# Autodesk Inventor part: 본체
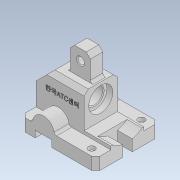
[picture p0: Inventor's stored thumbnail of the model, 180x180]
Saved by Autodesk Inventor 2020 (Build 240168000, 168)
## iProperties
Created: 2022-08
Part Number: 본체
Material: 일반
Document SubType Name: Modeling
Designer: user
Density: 1 g/cm^3
Appearance: 기본값
Author: user
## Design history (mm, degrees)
sketch "스케치1"
  geometry: L1 (32, -27)-(-58, -27); L2 (-58, -27)-(-58, -42); L3 (-58, -42)-(32, -42); L4 (32, -42)-(32, -27); L5 (32, -27)-(-58, -42); L6 (-58, -27)-(32, -42); C1 r 13 at (-31, -27); 4 further points
  constraints: 12 end point, 2 midpoint, 2 parallel, 1 centre point, 1 horizontal, 1 perpendicular, 1 point on line
  dimensions: "d0" = 15 distance of L1.end L2.end; "d1" = 90 distance of L2.end L3.end; "d2" = 26 diameter of C1; "d3" = 27 distance from line of C1.centre L2; "d4" = 42 distance from line of L3 point (0, 0); "d5" = 32 distance from line of L4 point (0, 0)
extrude "돌출1" new body sketch "스케치1" stored distance "d6" = 76; taper "d7" = 0 deg
sketch "스케치2"
  geometry: L1 (0, 18)-(-58, 18); L2 (-58, 18)-(-58, -27); L3 (-58, -27)-(0, -27); L4 (0, -27)-(0, 18); L5 (0, 18)-(-58, -27); L6 (-58, 18)-(0, -27); 3 further points
  constraints: 12 end point, 2 midpoint, 2 parallel, 1 coincident, 1 horizontal, 1 perpendicular, 1 vertical alignment
  dimensions: "d8" = 45 distance of L1.end L2.end
extrude "돌출2" join sketch "스케치2" stored distance "d9" = 40; taper "d10" = 0 deg
chamfer "모따기1" distance "d11" = 18; stored, may be unused: second distance "d12" = 2, angle "d13" = 45 deg
sketch "스케치3"
  geometry: C1 r 14.5 at (20, 27); 1 further point
  constraints: 1 centre point, 1 coincident
  dimensions: "d14" = 29 diameter of C1
extrude "돌출3" cut sketch "스케치3" distance "d15" = 7; taper "d16" = 0 deg
sketch "스케치4"
  geometry: C1 r 10 at (0, 0); 1 further point
  constraints: 1 centre point, 1 coincident
  dimensions: "d17" = 20 diameter of C1
extrude "돌출4" cut sketch "스케치4" extent not by distance; stored distance "d18" = 0; taper "d19" = 0 deg
sketch "스케치5"
  geometry: L1 (-5, 27.5)-(-29, 27.5); L2 (-29, 27.5)-(-29, 12.5); L3 (-29, 12.5)-(-5, 12.5); L4 (-5, 12.5)-(-5, 27.5); L5 (-5, 27.5)-(-29, 12.5); L6 (-29, 27.5)-(-5, 12.5); L7 (0, 40)-(0, 0) reference; 4 further points
  constraints: 12 end point, 4 midpoint, 2 parallel, 1 horizontal, 1 horizontal alignment, 1 perpendicular
  dimensions: "d20" = 5 distance between parallel lines of L7 L4; "d21" = 24 distance of L1.start L1.end; "d22" = 15 distance of L1.end L2.end
extrude "돌출5" join sketch "스케치5" distance "d23" = 30; taper "d24" = 0 deg
chamfer "모따기2" distance "d25" = 5; stored, may be unused: second distance "d26" = 2, angle "d27" = 45 deg
sketch "스케치6"
  geometry: L1 (24, 0)-(24, 25) reference; C1 r 4 at (12, 17); 1 further point
  constraints: 1 centre point
  dimensions: "d28" = 8 diameter of C1; "d29" = 35 vertical distance of C1.centre point (29, -18); "d30" = 12 distance from line of L1 C1.centre
extrude "돌출6" cut sketch "스케치6" extent not by distance; stored distance "d31" = 0; taper "d32" = 0 deg
chamfer "모따기3" distance "d33" = 1; stored, may be unused: second distance "d34" = 2, angle "d35" = 45 deg
sketch "스케치7"
  geometry: L1 (76, 15)-(0, 15) reference; L2 (58, 19)-(18, 19); L3 (18, 19)-(18, 15); L4 (18, 15)-(58, 15); L5 (58, 15)-(58, 19); L6 (58, 19)-(18, 15); L7 (18, 19)-(58, 15); L8 (18, 15)-(18, 60) reference; L9 (58, 60)-(58, 15) reference; L10 (58, 60)-(18, 60) reference; L11 (76, 0)-(0, 0) reference; 4 further points
  constraints: 12 end point, 2 midpoint, 2 parallel, 2 point on line, 1 horizontal, 1 perpendicular
  dimensions: "d36" = 45 distance between parallel lines of L4 L10; "d37" = 19 distance between parallel lines of L2 L11
extrude "돌출7" join sketch "스케치7" distance "d38" = 32; taper "d39" = 0 deg
sketch "스케치8"
  geometry: C1 r 29 at (38, 42); 1 further point
  constraints: 1 centre point, 1 coincident
  dimensions: "d40" = 58 diameter of C1
extrude "돌출8" cut sketch "스케치8" distance "d41" = 18; taper "d42" = 0 deg
sketch "스케치9"
  geometry: L1 (44, 19)-(32, 19); L2 (32, 19)-(32, 0); L3 (32, 0)-(44, 0); L4 (44, 0)-(44, 19); L5 (44, 19)-(32, 0); L6 (32, 19)-(44, 0); L7 (76, 0)-(0, 0) reference; L8 (20.336, 19)-(55.664, 19) reference; 3 further points
  constraints: 12 end point, 3 midpoint, 2 parallel, 2 point on line, 1 horizontal, 1 perpendicular, 1 vertical alignment
  dimensions: "d43" = 12 distance of L2.end L3.end
extrude "돌출9" cut sketch "스케치9" distance "d44" = 18; taper "d45" = 0 deg
sketch "스케치10"
  geometry: L1 (50, 76)-(50, 58) reference; 3 further points
  constraints: 1 vertical alignment
  dimensions: "d46" = 13 distance from line of L1 point (37, 68); "d47" = 30 vertical distance of point (37, 68) point (18, 38); "d48" = 60 distance of point (37, 8) point (37, 68)
hole "구멍1" sketch "스케치10" at (37, 68), (37, 8) diameter "d49" = 4.5; stored, may be unused: countersink angle "d53" = 90 deg, drill point angle "d55" = 118 deg; dims "d50" = 6, "d51" = 8, "d52" = 4.4, "d54" = 8
chamfer "모따기4" distance "d56" = 5; stored, may be unused: second distance "d57" = 2, angle "d58" = 45 deg
sketch "스케치11"
  geometry: L1 (-21, -34)-(-41, -34); L2 (-41, -34)-(-41, -42); L3 (-41, -42)-(-21, -42); L4 (-21, -42)-(-21, -34); L5 (-21, -34)-(-41, -42); L6 (-41, -34)-(-21, -42); L7 (-58, -27)-(-58, -42) reference; L8 (-53, -42)-(27, -42) reference; 2 further points
  constraints: 12 end point, 2 midpoint, 2 parallel, 1 horizontal, 1 perpendicular, 1 point on line
  dimensions: "d59" = 27 distance from line of point (-31, -38) L7; "d60" = 20 distance of L1.start L1.end; "d61" = 8 distance of L1.end L2.end
extrude "돌출10" cut sketch "스케치11" extent not by distance; stored distance "d62" = 0; taper "d63" = 0 deg
chamfer "모따기5" distance "d64" = 5; stored, may be unused: second distance "d65" = 2, angle "d66" = 45 deg
fillet "모깎기1" dims "d67" = 3
fillet "모깎기2" dims "d68" = 3
node "작업 평면1"
sketch "스케치12"
  geometry: L1 (0, -23)-(0, 13) reference; L2 (0, 18)-(-40, 18) reference; 2 further points
  constraints: 1 other
  dimensions: "d70" = 26 distance from line of L1 point (-26, 0); "d71" = 18 distance from line of L2 point (-26, 0)
feature "엠보싱1" sketch "스케치12" dims "d0" = 15, "d1" = 90, "d2" = 26, "d3" = 27, "d4" = 42, "d5" = 32, "d72" = 0.5, "d73" = 0
node "솔리드1"
other parameters: "d69" = 96
